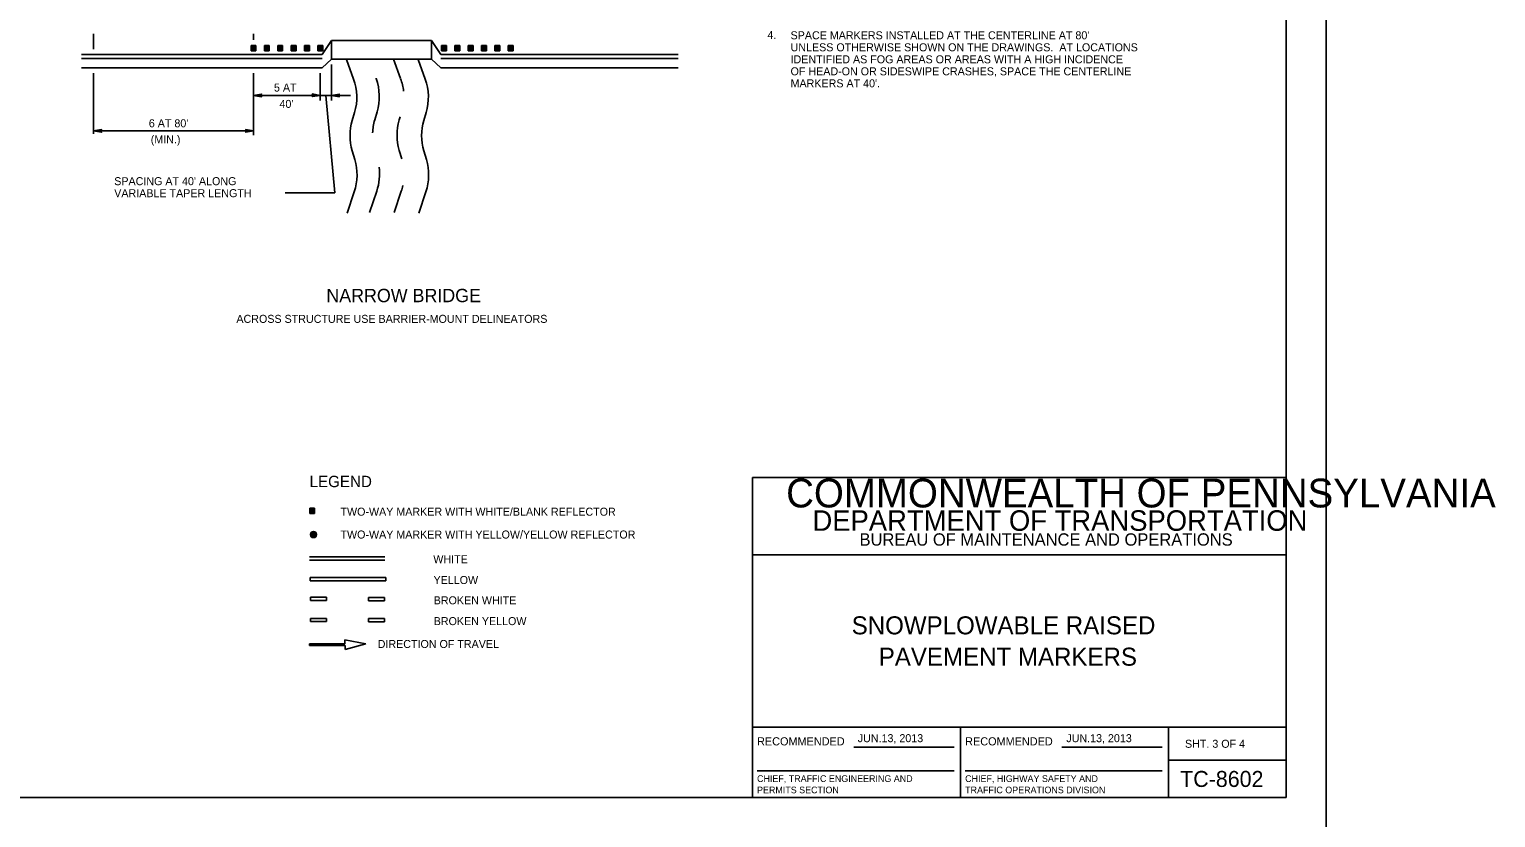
# Model space of a CAD drawing. Extents: x 639362 to 641108, y 298458 to 299646.
# Drawn here: x 640558 to 641108, y 299059 to 299354 of the extents above; entities that cross this region are included whole.
import ezdxf

# ---------------------------------------------------------------- set-up
doc = ezdxf.new("R2010")
doc.units = 0
for name, color, linetype in [('1', 7, 'Continuous'), ('2', 7, 'Continuous'), ('3', 7, 'Continuous'), ('Level 1', 7, 'Continuous'), ('PLT-BNDY', 7, 'Continuous')]:
    doc.layers.add(name, color=color, linetype=linetype)

# ---------------------------------------------------------------- blocks, each defined once
blk = doc.blocks.new('RARROW')
at = {"layer": '3'}
blk.add_lwpolyline([(-2.2695, 0.285), (-2.184875, 0.12075), (0, 0), (-2.2695, 0.285), (-2.38575, 0.384625), (0, 0), (-2.183125, -0.108), (-2.262875, -0.2705), (0, 0), (-2.38575, -0.379125), (-2.262875, -0.2705)], dxfattribs=at)

msp = doc.modelspace()

# ---------------------------------------------------------------- linework, layer by layer
at = {"layer": '1'}
for p, q in [((641029.31, 299066.63), (641029.31, 299630.63)), ((640829.31, 299066.63), (640829.31, 299186.63)), ((640829.31, 299186.63), (641029.31, 299186.63)), ((641029.31, 299157.63), (640829.31, 299157.63)), ((640829.31, 299093), (641029.31, 299093)), ((640907.31, 299093), (640907.31, 299066.63)), ((640985.19, 299066.63), (640985.19, 299093)), ((640867.24, 299085.57), (640904.87, 299085.57)), ((640945.24, 299085.57), (640982.87, 299085.57)), ((640985.19, 299080.63), (641029.31, 299080.63)), ((641029.31, 299066.63), (640243.31, 299066.63)), ((640243.31, 299066.63), (640829.31, 299066.63))]:
    msp.add_line(p, q, dxfattribs=at)
at = {"layer": '2'}
for p, q in [((640582.27, 299347.07), (640582.27, 299352.76)), ((640641.38, 299348.5), (640643.16, 299348.5)), ((640641.38, 299346.46), (640641.38, 299348.5)), ((640641.56, 299348.32), (640642.98, 299348.32)), ((640641.56, 299346.63), (640641.56, 299348.32)), ((640641.74, 299348.14), (640642.8, 299348.14)), ((640641.74, 299346.81), (640641.74, 299348.14)), ((640641.91, 299346.99), (640641.91, 299347.96)), ((640641.91, 299347.96), (640642.62, 299347.96)), ((640642.09, 299347.79), (640642.45, 299347.79)), ((640642.09, 299347.17), (640642.09, 299347.79)), ((640642.27, 299350.54), (640642.27, 299352.76)), ((640642.27, 299347.61), (640642.27, 299347.34)), ((640642.45, 299347.79), (640642.45, 299347.17)), ((640642.62, 299347.96), (640642.62, 299346.99)), ((640642.8, 299348.14), (640642.8, 299346.81)), ((640642.98, 299348.32), (640642.98, 299346.63)), ((640643.16, 299348.5), (640643.16, 299346.46)), ((640646.38, 299348.5), (640648.16, 299348.5)), ((640646.38, 299346.46), (640646.38, 299348.5)), ((640646.56, 299348.32), (640647.98, 299348.32)), ((640646.56, 299346.63), (640646.56, 299348.32)), ((640646.74, 299348.14), (640647.8, 299348.14)), ((640646.74, 299346.81), (640646.74, 299348.14)), ((640646.91, 299346.99), (640646.91, 299347.96)), ((640646.91, 299347.96), (640647.62, 299347.96)), ((640647.09, 299347.79), (640647.45, 299347.79)), ((640647.09, 299347.17), (640647.09, 299347.79)), ((640647.27, 299347.61), (640647.27, 299347.34)), ((640647.45, 299347.79), (640647.45, 299347.17)), ((640647.62, 299347.96), (640647.62, 299346.99)), ((640647.8, 299348.14), (640647.8, 299346.81)), ((640647.98, 299348.32), (640647.98, 299346.63)), ((640648.16, 299348.5), (640648.16, 299346.46)), ((640651.38, 299348.49), (640653.16, 299348.49)), ((640651.38, 299346.45), (640651.38, 299348.49)), ((640651.56, 299348.32), (640652.98, 299348.32)), ((640651.56, 299346.63), (640651.56, 299348.32)), ((640651.74, 299348.14), (640652.8, 299348.14)), ((640651.74, 299346.81), (640651.74, 299348.14)), ((640651.91, 299346.99), (640651.91, 299347.96)), ((640651.91, 299347.96), (640652.62, 299347.96)), ((640652.09, 299347.79), (640652.45, 299347.79)), ((640652.09, 299347.16), (640652.09, 299347.79)), ((640652.27, 299347.61), (640652.27, 299347.34)), ((640652.45, 299347.79), (640652.45, 299347.16)), ((640652.62, 299347.96), (640652.62, 299346.99)), ((640652.8, 299348.14), (640652.8, 299346.81)), ((640652.98, 299348.32), (640652.98, 299346.63)), ((640653.16, 299348.49), (640653.16, 299346.45)), ((640656.38, 299348.49), (640658.16, 299348.49)), ((640656.38, 299346.45), (640656.38, 299348.49)), ((640656.56, 299348.31), (640657.98, 299348.31)), ((640656.56, 299346.63), (640656.56, 299348.31)), ((640656.74, 299348.14), (640657.8, 299348.14)), ((640656.74, 299346.81), (640656.74, 299348.14)), ((640656.91, 299346.99), (640656.91, 299347.96)), ((640656.91, 299347.96), (640657.62, 299347.96)), ((640657.09, 299347.78), (640657.45, 299347.78)), ((640657.09, 299347.16), (640657.09, 299347.78)), ((640657.27, 299347.61), (640657.27, 299347.34)), ((640657.45, 299347.78), (640657.45, 299347.16)), ((640657.62, 299347.96), (640657.62, 299346.99)), ((640657.8, 299348.14), (640657.8, 299346.81)), ((640657.98, 299348.31), (640657.98, 299346.63)), ((640658.16, 299348.49), (640658.16, 299346.45)), ((640661.38, 299348.49), (640663.16, 299348.49)), ((640661.38, 299346.45), (640661.38, 299348.49)), ((640661.56, 299348.31), (640662.98, 299348.31)), ((640661.56, 299346.63), (640661.56, 299348.31)), ((640661.74, 299348.14), (640662.8, 299348.14)), ((640661.74, 299346.81), (640661.74, 299348.14)), ((640661.91, 299346.98), (640661.91, 299347.96)), ((640661.91, 299347.96), (640662.62, 299347.96)), ((640662.09, 299347.78), (640662.45, 299347.78)), ((640662.09, 299347.16), (640662.09, 299347.78)), ((640662.27, 299347.61), (640662.27, 299347.34)), ((640662.45, 299347.78), (640662.45, 299347.16)), ((640662.62, 299347.96), (640662.62, 299346.98)), ((640662.8, 299348.14), (640662.8, 299346.81)), ((640662.98, 299348.31), (640662.98, 299346.63)), ((640663.16, 299348.49), (640663.16, 299346.45)), ((640666.38, 299348.49), (640668.16, 299348.49)), ((640666.38, 299346.45), (640666.38, 299348.49)), ((640666.56, 299348.31), (640667.98, 299348.31)), ((640666.56, 299346.63), (640666.56, 299348.31)), ((640666.74, 299348.13), (640667.8, 299348.13)), ((640666.74, 299346.81), (640666.74, 299348.13)), ((640666.91, 299346.98), (640666.91, 299347.96)), ((640666.91, 299347.96), (640667.62, 299347.96)), ((640667.09, 299347.78), (640667.45, 299347.78)), ((640667.09, 299347.16), (640667.09, 299347.78)), ((640667.27, 299347.61), (640667.27, 299347.34)), ((640667.45, 299347.78), (640667.45, 299347.16)), ((640667.62, 299347.96), (640667.62, 299346.98)), ((640667.8, 299348.13), (640667.8, 299346.81)), ((640667.94, 299345.07), (640671.45, 299350.34)), ((640667.98, 299348.31), (640667.98, 299346.63)), ((640668.16, 299348.49), (640668.16, 299346.45)), ((640671.45, 299350.34), (640708.95, 299350.34)), ((640671.45, 299350.34), (640671.45, 299343.31)), ((640712.47, 299345.07), (640708.95, 299350.34)), ((640708.95, 299350.34), (640708.95, 299343.31)), ((640712.75, 299348.49), (640714.52, 299348.49)), ((640712.75, 299346.45), (640712.75, 299348.49)), ((640712.92, 299348.31), (640714.34, 299348.31)), ((640712.92, 299346.63), (640712.92, 299348.31)), ((640713.1, 299348.13), (640714.17, 299348.13)), ((640713.1, 299346.81), (640713.1, 299348.13)), ((640713.28, 299346.98), (640713.28, 299347.96)), ((640713.28, 299347.96), (640713.99, 299347.96)), ((640713.46, 299347.78), (640713.81, 299347.78)), ((640713.46, 299347.16), (640713.46, 299347.78)), ((640713.63, 299347.61), (640713.63, 299347.34)), ((640713.81, 299347.78), (640713.81, 299347.16)), ((640713.99, 299347.96), (640713.99, 299346.98)), ((640714.17, 299348.13), (640714.17, 299346.81)), ((640714.34, 299348.31), (640714.34, 299346.63)), ((640714.52, 299348.49), (640714.52, 299346.45)), ((640717.75, 299348.49), (640719.52, 299348.49)), ((640717.75, 299346.45), (640717.75, 299348.49)), ((640717.92, 299348.31), (640719.34, 299348.31)), ((640717.92, 299346.63), (640717.92, 299348.31)), ((640718.1, 299348.13), (640719.17, 299348.13)), ((640718.1, 299346.81), (640718.1, 299348.13)), ((640718.28, 299346.98), (640718.28, 299347.96)), ((640718.28, 299347.96), (640718.99, 299347.96)), ((640718.46, 299347.78), (640718.81, 299347.78)), ((640718.46, 299347.16), (640718.46, 299347.78)), ((640718.63, 299347.6), (640718.63, 299347.34)), ((640718.81, 299347.78), (640718.81, 299347.16)), ((640718.99, 299347.96), (640718.99, 299346.98)), ((640719.17, 299348.13), (640719.17, 299346.81)), ((640719.34, 299348.31), (640719.34, 299346.63)), ((640719.52, 299348.49), (640719.52, 299346.45)), ((640722.75, 299348.49), (640724.52, 299348.49)), ((640722.75, 299346.45), (640722.75, 299348.49)), ((640722.92, 299348.31), (640724.34, 299348.31)), ((640722.92, 299346.63), (640722.92, 299348.31)), ((640723.1, 299348.13), (640724.17, 299348.13)), ((640723.1, 299346.8), (640723.1, 299348.13)), ((640723.28, 299346.98), (640723.28, 299347.96)), ((640723.28, 299347.96), (640723.99, 299347.96)), ((640723.46, 299347.78), (640723.81, 299347.78)), ((640723.46, 299347.16), (640723.46, 299347.78)), ((640723.63, 299347.6), (640723.63, 299347.33)), ((640723.81, 299347.78), (640723.81, 299347.16)), ((640723.99, 299347.96), (640723.99, 299346.98)), ((640724.17, 299348.13), (640724.17, 299346.8)), ((640724.34, 299348.31), (640724.34, 299346.63)), ((640724.52, 299348.49), (640724.52, 299346.45)), ((640727.75, 299348.49), (640729.52, 299348.49)), ((640727.75, 299346.45), (640727.75, 299348.49)), ((640727.92, 299348.31), (640729.34, 299348.31)), ((640727.92, 299346.62), (640727.92, 299348.31)), ((640728.1, 299348.13), (640729.17, 299348.13)), ((640728.1, 299346.8), (640728.1, 299348.13)), ((640728.28, 299346.98), (640728.28, 299347.95)), ((640728.28, 299347.95), (640728.99, 299347.95)), ((640728.46, 299347.78), (640728.81, 299347.78)), ((640728.46, 299347.16), (640728.46, 299347.78)), ((640728.63, 299347.6), (640728.63, 299347.33)), ((640728.81, 299347.78), (640728.81, 299347.16)), ((640728.99, 299347.95), (640728.99, 299346.98)), ((640729.17, 299348.13), (640729.17, 299346.8)), ((640729.34, 299348.31), (640729.34, 299346.62)), ((640729.52, 299348.49), (640729.52, 299346.45)), ((640732.75, 299348.49), (640734.52, 299348.49)), ((640732.75, 299346.45), (640732.75, 299348.49)), ((640732.92, 299348.31), (640734.34, 299348.31)), ((640732.92, 299346.62), (640732.92, 299348.31)), ((640733.1, 299348.13), (640734.17, 299348.13)), ((640733.1, 299346.8), (640733.1, 299348.13)), ((640733.28, 299346.98), (640733.28, 299347.95)), ((640733.28, 299347.95), (640733.99, 299347.95)), ((640733.46, 299347.78), (640733.81, 299347.78)), ((640733.46, 299347.16), (640733.46, 299347.78)), ((640733.63, 299347.6), (640733.63, 299347.33)), ((640733.81, 299347.78), (640733.81, 299347.16)), ((640733.99, 299347.95), (640733.99, 299346.98)), ((640734.17, 299348.13), (640734.17, 299346.8)), ((640734.34, 299348.31), (640734.34, 299346.62)), ((640734.52, 299348.49), (640734.52, 299346.45)), ((640737.75, 299348.48), (640739.52, 299348.48)), ((640737.75, 299346.44), (640737.75, 299348.48)), ((640737.92, 299348.31), (640739.34, 299348.31)), ((640737.92, 299346.62), (640737.92, 299348.31)), ((640738.1, 299348.13), (640739.17, 299348.13)), ((640738.1, 299346.8), (640738.1, 299348.13)), ((640738.28, 299346.98), (640738.28, 299347.95)), ((640738.28, 299347.95), (640738.99, 299347.95)), ((640738.46, 299347.78), (640738.81, 299347.78)), ((640738.46, 299347.15), (640738.46, 299347.78)), ((640738.63, 299347.6), (640738.63, 299347.33)), ((640738.81, 299347.78), (640738.81, 299347.15)), ((640738.99, 299347.95), (640738.99, 299346.98)), ((640739.17, 299348.13), (640739.17, 299346.8)), ((640739.34, 299348.31), (640739.34, 299346.62)), ((640739.52, 299348.48), (640739.52, 299346.44)), ((640577.74, 299345.07), (640667.94, 299345.07)), ((640577.74, 299343.57), (640667.94, 299343.57)), ((640643.16, 299346.46), (640641.38, 299346.46)), ((640642.98, 299346.63), (640641.56, 299346.63)), ((640642.8, 299346.81), (640641.74, 299346.81)), ((640642.62, 299346.99), (640641.91, 299346.99)), ((640642.45, 299347.17), (640642.09, 299347.17)), ((640648.16, 299346.46), (640646.38, 299346.46)), ((640647.98, 299346.63), (640646.56, 299346.63)), ((640647.8, 299346.81), (640646.74, 299346.81)), ((640647.62, 299346.99), (640646.91, 299346.99)), ((640647.45, 299347.17), (640647.09, 299347.17)), ((640653.16, 299346.45), (640651.38, 299346.45)), ((640652.98, 299346.63), (640651.56, 299346.63)), ((640652.8, 299346.81), (640651.74, 299346.81)), ((640652.62, 299346.99), (640651.91, 299346.99)), ((640652.45, 299347.16), (640652.09, 299347.16)), ((640658.16, 299346.45), (640656.38, 299346.45)), ((640657.98, 299346.63), (640656.56, 299346.63)), ((640657.8, 299346.81), (640656.74, 299346.81)), ((640657.62, 299346.99), (640656.91, 299346.99)), ((640657.45, 299347.16), (640657.09, 299347.16)), ((640663.16, 299346.45), (640661.38, 299346.45)), ((640662.98, 299346.63), (640661.56, 299346.63)), ((640662.8, 299346.81), (640661.74, 299346.81)), ((640662.62, 299346.98), (640661.91, 299346.98)), ((640662.45, 299347.16), (640662.09, 299347.16)), ((640668.16, 299346.45), (640666.38, 299346.45)), ((640667.98, 299346.63), (640666.56, 299346.63)), ((640667.8, 299346.81), (640666.74, 299346.81)), ((640667.62, 299346.98), (640666.91, 299346.98)), ((640667.45, 299347.16), (640667.09, 299347.16)), ((640667.94, 299340.07), (640671.45, 299343.31)), ((640671.45, 299343.31), (640708.95, 299343.31)), ((640679.74, 299335.87), (640677.07, 299343.23)), ((640697.39, 299336.02), (640694.71, 299343.37)), ((640706.59, 299335.87), (640703.91, 299343.23)), ((640712.47, 299340.07), (640708.95, 299343.31)), ((640712.47, 299345.07), (640801.44, 299345.07)), ((640712.47, 299343.57), (640801.44, 299343.57)), ((640714.52, 299346.45), (640712.75, 299346.45)), ((640714.34, 299346.63), (640712.92, 299346.63)), ((640714.17, 299346.81), (640713.1, 299346.81)), ((640713.99, 299346.98), (640713.28, 299346.98)), ((640713.81, 299347.16), (640713.46, 299347.16)), ((640719.52, 299346.45), (640717.75, 299346.45)), ((640719.34, 299346.63), (640717.92, 299346.63)), ((640719.17, 299346.81), (640718.1, 299346.81)), ((640718.99, 299346.98), (640718.28, 299346.98)), ((640718.81, 299347.16), (640718.46, 299347.16)), ((640724.52, 299346.45), (640722.75, 299346.45)), ((640724.34, 299346.63), (640722.92, 299346.63)), ((640724.17, 299346.8), (640723.1, 299346.8)), ((640723.99, 299346.98), (640723.28, 299346.98)), ((640723.81, 299347.16), (640723.46, 299347.16)), ((640729.52, 299346.45), (640727.75, 299346.45)), ((640729.34, 299346.62), (640727.92, 299346.62)), ((640729.17, 299346.8), (640728.1, 299346.8)), ((640728.99, 299346.98), (640728.28, 299346.98)), ((640728.81, 299347.16), (640728.46, 299347.16)), ((640734.52, 299346.45), (640732.75, 299346.45)), ((640734.34, 299346.62), (640732.92, 299346.62)), ((640734.17, 299346.8), (640733.1, 299346.8)), ((640733.99, 299346.98), (640733.28, 299346.98)), ((640733.81, 299347.16), (640733.46, 299347.16)), ((640739.52, 299346.44), (640737.75, 299346.44)), ((640739.34, 299346.62), (640737.92, 299346.62)), ((640739.17, 299346.8), (640738.1, 299346.8)), ((640738.99, 299346.98), (640738.28, 299346.98)), ((640738.81, 299347.15), (640738.46, 299347.15)), ((640577.74, 299340.07), (640667.94, 299340.07)), ((640582.26, 299315.37), (640582.26, 299338.07)), ((640642.26, 299314.79), (640642.26, 299338.07)), ((640667.26, 299327.81), (640667.26, 299338.07)), ((640671.45, 299327.8), (640671.45, 299341.31)), ((640712.47, 299340.07), (640801.44, 299340.07)), ((640688.19, 299336.08), (640688.16, 299336.16)), ((640667.26, 299329.77), (640642.26, 299329.77)), ((640678.56, 299329.77), (640667.26, 299329.77)), ((640672.76, 299293.3), (640669.31, 299329.77)), ((640679.24, 299320.39), (640680.12, 299323.32)), ((640687.68, 299320.6), (640688.56, 299323.54)), ((640696.89, 299320.54), (640697.23, 299321.69)), ((640706.09, 299320.39), (640706.96, 299323.32)), ((640642.26, 299316.45), (640582.26, 299316.46)), ((640680.21, 299305.72), (640679.23, 299309)), ((640697.82, 299305.96), (640696.88, 299309.14)), ((640707.05, 299305.72), (640706.08, 299309)), ((640672.76, 299293.3), (640654.16, 299293.3)), ((640677.31, 299285.68), (640679.99, 299293.67)), ((640685.75, 299285.9), (640688.43, 299293.88)), ((640694.95, 299285.83), (640697.63, 299293.81)), ((640704.15, 299285.68), (640706.83, 299293.67)), ((640663.35, 299175.09), (640665.13, 299175.09)), ((640663.35, 299173.05), (640663.35, 299175.09)), ((640665.13, 299173.05), (640663.35, 299173.05)), ((640663.53, 299174.91), (640664.95, 299174.91)), ((640663.53, 299173.22), (640663.53, 299174.91)), ((640664.95, 299173.22), (640663.53, 299173.22)), ((640663.71, 299174.73), (640664.77, 299174.73)), ((640663.71, 299173.4), (640663.71, 299174.73)), ((640664.77, 299173.4), (640663.71, 299173.4)), ((640663.89, 299173.58), (640663.89, 299174.55)), ((640663.89, 299174.55), (640664.59, 299174.55)), ((640664.59, 299173.58), (640663.89, 299173.58)), ((640664.06, 299174.38), (640664.42, 299174.38)), ((640664.06, 299173.76), (640664.06, 299174.38)), ((640664.42, 299173.76), (640664.06, 299173.76)), ((640664.24, 299174.2), (640664.24, 299173.93)), ((640664.42, 299174.38), (640664.42, 299173.76)), ((640664.59, 299174.55), (640664.59, 299173.58)), ((640664.77, 299174.73), (640664.77, 299173.4)), ((640664.95, 299174.91), (640664.95, 299173.22)), ((640665.13, 299175.09), (640665.13, 299173.05)), ((640691.51, 299156.85), (640663.23, 299156.85)), ((640691.51, 299155.65), (640663.23, 299155.65)), ((640691.78, 299149.09), (640663.5, 299149.09)), ((640663.5, 299149.09), (640663.5, 299147.89)), ((640663.5, 299147.89), (640691.78, 299147.89)), ((640691.78, 299147.89), (640691.78, 299149.09)), ((640669.6, 299141.71), (640663.58, 299141.71)), ((640663.58, 299141.71), (640663.58, 299140.51)), ((640663.58, 299140.51), (640669.6, 299140.51)), ((640669.6, 299140.51), (640669.6, 299141.71)), ((640691.32, 299141.61), (640685.3, 299141.61)), ((640685.3, 299141.61), (640685.3, 299140.41)), ((640685.3, 299140.41), (640691.32, 299140.41)), ((640691.32, 299140.41), (640691.32, 299141.61)), ((640663.61, 299133.81), (640663.61, 299132.61)), ((640669.62, 299133.81), (640663.61, 299133.81)), ((640669.62, 299132.61), (640669.62, 299133.81)), ((640685.33, 299133.71), (640685.33, 299132.51)), ((640691.34, 299133.71), (640685.33, 299133.71)), ((640691.34, 299132.51), (640691.34, 299133.71)), ((640663.61, 299132.61), (640669.62, 299132.61)), ((640685.33, 299132.51), (640691.34, 299132.51)), ((640676.5, 299124.3), (640663.26, 299124.3)), ((640663.26, 299124.3), (640663.26, 299123.59)), ((640663.26, 299123.59), (640676.58, 299123.59)), ((640684.31, 299124.26), (640676.5, 299125.74)), ((640676.5, 299125.74), (640676.5, 299124.3)), ((640676.58, 299122.15), (640684.31, 299124.26)), ((640676.58, 299123.59), (640676.58, 299122.15))]:
    msp.add_line(p, q, dxfattribs=at)
for radius in [1.15, 1.07, 0.985, 0.904, 0.822, 0.741, 0.659, 0.578, 0.496, 0.414, 0.333, 0.251, 0.17, 0.0881]:
    msp.add_circle((640664.72, 299165.21), radius, dxfattribs=at)
for centre, start, end in [((640660.95, 299329.03), 343.4142, 19.9879), ((640669.39, 299329.25), 343.4142, 19.9879), ((640678.59, 299329.18), 6.1927, 19.9879), ((640687.79, 299329.03), 343.4142, 19.9879), ((640698.41, 299314.68), 163.4142, 196.5084), ((640706.85, 299314.89), 163.4142, 177.785), ((640716.05, 299314.83), 163.4142, 196.5084), ((640725.26, 299314.68), 163.4142, 196.5084), ((640661.03, 299300.04), 341.4259, 16.5084), ((640687.88, 299300.04), 341.4259, 16.5084), ((640669.47, 299300.25), 341.4259, 7.3864), ((640678.67, 299300.18), 341.4259, 347.8196)]:
    msp.add_arc(centre, 20, start, end, dxfattribs=at)
at = {"layer": 'Level 1'}
for p, q in [((640830.99, 299076.68), (640904.87, 299076.68)), ((640908.99, 299076.68), (640982.87, 299076.68))]:
    msp.add_line(p, q, dxfattribs=at)
at = {"layer": 'PLT-BNDY'}
msp.add_lwpolyline([(640203.31, 299645.63), (641044.31, 299645.63), (641044.31, 299051.63), (640203.31, 299051.63)], close=True, dxfattribs=at)

# ---------------------------------------------------------------- block references
at = {"layer": '2', "xscale": 1.2574347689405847, "yscale": 1.3092961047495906, "rotation": 180}
for p in [(640642.26, 299329.77), (640671.45, 299329.77), (640582.26, 299316.46)]:
    msp.add_blockref('RARROW', p, dxfattribs=at)
at = {"layer": '2', "xscale": 1.2574347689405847, "yscale": 1.3092961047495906}
for p in [(640667.26, 299329.77), (640642.26, 299316.45)]:
    msp.add_blockref('RARROW', p, dxfattribs=at)

# ---------------------------------------------------------------- texts
at = {"layer": '1'}
for s, height, p in [('COMMONWEALTH OF PENNSYLVANIA', 10.7828, (640841.9, 299175.36)), ('DEPARTMENT OF TRANSPORTATION', 7.6837, (640851.76, 299166.61)), ('BUREAU OF MAINTENANCE AND OPERATIONS', 4.6253, (640869.41, 299161.04)), ('SNOWPLOWABLE RAISED', 6.75, (640866.46, 299127.81)), ('PAVEMENT MARKERS', 6.75, (640876.61, 299116.06)), ('RECOMMENDED', 3.048, (640830.99, 299086.2)), ('JUN.13, 2013', 3, (640868.73, 299087.41)), ('RECOMMENDED', 3.048, (640908.99, 299086.2)), ('JUN.13, 2013', 3, (640946.92, 299087.41)), ('SHT. 3 OF 4', 3, (640991.4, 299085.31)), ('TC-8602', 6, (640989.6, 299070.63))]:
    msp.add_text(s, height=height, dxfattribs=at).set_placement(p)
at = {"layer": '2'}
for s, height, p in [('4. ', 3, (640834.87, 299350.89)), ("SPACE MARKERS INSTALLED AT THE CENTERLINE AT 80'", 3, (640843.55, 299350.77)), ('UNLESS OTHERWISE SHOWN ON THE DRAWINGS.  AT LOCATIONS', 3, (640843.55, 299346.27)), ('IDENTIFIED AS FOG AREAS OR AREAS WITH A HIGH INCIDENCE', 3, (640843.55, 299341.77)), ('OF HEAD-ON OR SIDESWIPE CRASHES, SPACE THE CENTERLINE', 3, (640843.55, 299337.27)), ('5 AT', 3, (640649.91, 299331.18)), ("MARKERS AT 40'.", 3, (640843.55, 299332.77)), ("40'", 3, (640651.96, 299325.06)), ("6 AT 80'", 3, (640602.99, 299317.8)), (' (MIN.)', 3, (640602.6, 299311.77)), ("SPACING AT 40' ALONG", 3, (640590.02, 299296.11)), ('VARIABLE TAPER LENGTH', 3, (640590.02, 299291.61)), ('NARROW BRIDGE', 5, (640669.54, 299252.27)), ('ACROSS STRUCTURE USE BARRIER-MOUNT DELINEATORS', 3, (640635.82, 299244.52)), ('LEGEND', 4.25, (640663.25, 299182.97)), ('TWO-WAY MARKER WITH WHITE/BLANK REFLECTOR', 3, (640674.83, 299172.27)), ('WHITE', 3, (640709.63, 299154.47)), ('YELLOW', 3, (640709.71, 299146.67)), ('BROKEN WHITE', 3, (640709.78, 299139.06)), ('BROKEN YELLOW', 3, (640709.78, 299131.27)), ('DIRECTION OF TRAVEL', 3, (640688.78, 299122.7))]:
    msp.add_text(s, height=height, dxfattribs=at).set_placement(p)
msp.add_text('TWO-WAY MARKER WITH YELLOW/YELLOW REFLECTOR', height=3, rotation=360, dxfattribs=at).set_placement((640674.83, 299163.71))
at = {"layer": 'Level 1'}
for s, p in [('CHIEF, TRAFFIC ENGINEERING AND', (640830.99, 299072.51)), ('CHIEF, HIGHWAY SAFETY AND', (640908.99, 299072.51)), ('PERMITS SECTION', (640830.99, 299068.26)), ('TRAFFIC OPERATIONS DIVISION', (640908.99, 299068.26))]:
    msp.add_text(s, height=2.5, dxfattribs=at).set_placement(p)

doc.saveas('drawing.dxf')
